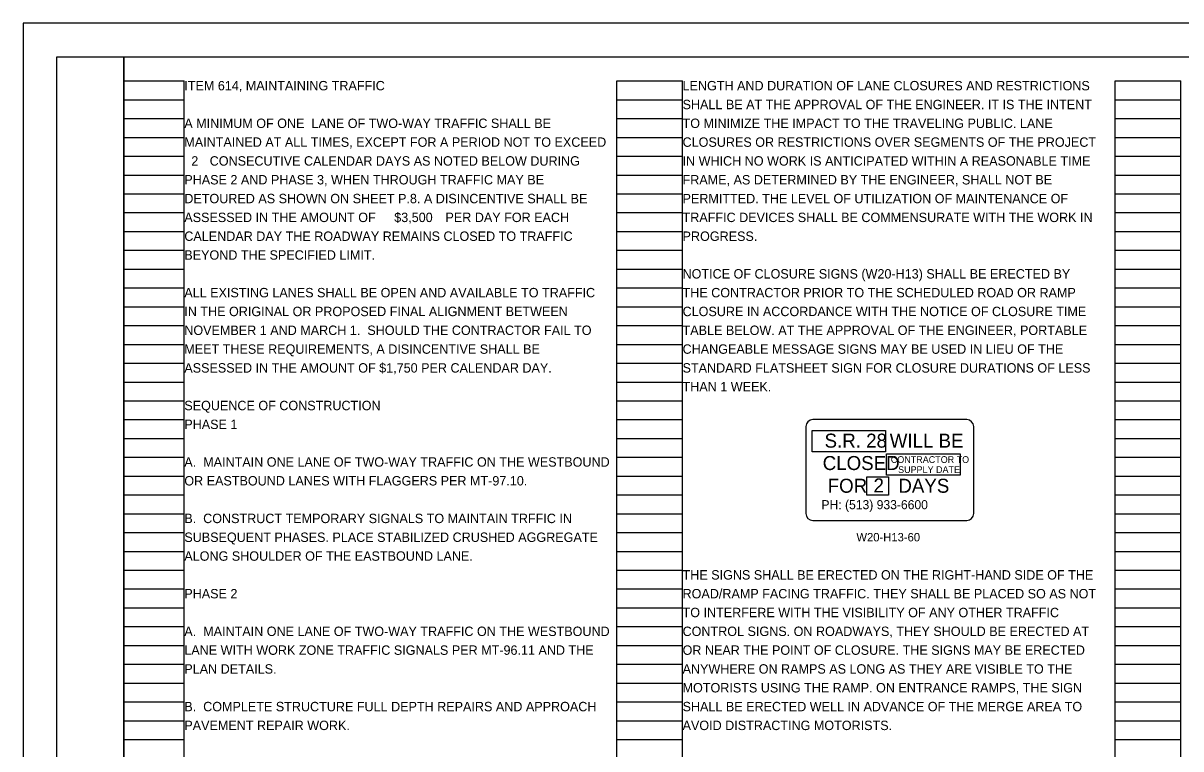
# Model space of a CAD drawing. Extents: x 0 to 34, y 0 to 33.4.
# Drawn here: x 0 to 17.24, y 11.2 to 22 of the extents above; entities that cross this region are included whole.
import ezdxf

# ---------------------------------------------------------------- set-up
doc = ezdxf.new("R2010")
doc.units = 0
for name, color, linetype in [('SH_Border', 7, 'Continuous'), ('SH_Cut_Line', 7, 'Continuous'), ('SH_Data', 7, 'Continuous'), ('SN_P_Signs', 7, 'Continuous'), ('SN_P_Text', 7, 'Continuous'), ('TX_X_20', 7, 'Continuous')]:
    doc.layers.add(name, color=color, linetype=linetype)

msp = doc.modelspace()

# ---------------------------------------------------------------- linework, layer by layer
at = {"layer": 'SH_Border'}
for points in [[(0.5, 21.5), (1.5, 21.5), (1.5, 0.5), (0.5, 0.5)], [(1.5, 21.5), (33.5, 21.5), (33.5, 0.5), (1.5, 0.5)]]:
    msp.add_lwpolyline(points, close=True, dxfattribs=at)
at = {"layer": 'SH_Cut_Line'}
msp.add_lwpolyline([(0, 0), (34, 0), (34, 22), (0, 22)], close=True, dxfattribs=at)
at = {"layer": 'SH_Data'}
for p, q in [((1.5, 0.98), (1.5, 21.14)), ((1.5, 21.14), (2.4, 21.14)), ((2.4, 0.98), (2.4, 21.14)), ((8.84, 0.98), (8.84, 21.14)), ((8.84, 21.14), (9.82, 21.14)), ((9.82, 0.98), (9.82, 21.14)), ((16.26, 0.98), (16.26, 21.14)), ((16.26, 21.14), (17.24, 21.14)), ((17.24, 0.98), (17.24, 21.14)), ((1.5, 20.86), (2.4, 20.86)), ((8.84, 20.86), (9.82, 20.86)), ((16.26, 20.86), (17.24, 20.86)), ((1.5, 20.58), (2.4, 20.58)), ((8.84, 20.58), (9.82, 20.58)), ((16.26, 20.58), (17.24, 20.58)), ((1.5, 20.3), (2.4, 20.3)), ((8.84, 20.3), (9.82, 20.3)), ((16.26, 20.3), (17.24, 20.3)), ((1.5, 20.02), (2.4, 20.02)), ((8.84, 20.02), (9.82, 20.02)), ((16.26, 20.02), (17.24, 20.02)), ((1.5, 19.74), (2.4, 19.74)), ((8.84, 19.74), (9.82, 19.74)), ((16.26, 19.74), (17.24, 19.74)), ((1.5, 19.46), (2.4, 19.46)), ((8.84, 19.46), (9.82, 19.46)), ((16.26, 19.46), (17.24, 19.46)), ((1.5, 19.18), (2.4, 19.18)), ((8.84, 19.18), (9.82, 19.18)), ((16.26, 19.18), (17.24, 19.18)), ((1.5, 18.9), (2.4, 18.9)), ((8.84, 18.9), (9.82, 18.9)), ((16.26, 18.9), (17.24, 18.9)), ((1.5, 18.62), (2.4, 18.62)), ((8.84, 18.62), (9.82, 18.62)), ((16.26, 18.62), (17.24, 18.62)), ((1.5, 18.34), (2.4, 18.34)), ((8.84, 18.34), (9.82, 18.34)), ((16.26, 18.34), (17.24, 18.34)), ((1.5, 18.06), (2.4, 18.06)), ((8.84, 18.06), (9.82, 18.06)), ((16.26, 18.06), (17.24, 18.06)), ((1.5, 17.78), (2.4, 17.78)), ((8.84, 17.78), (9.82, 17.78)), ((16.26, 17.78), (17.24, 17.78)), ((1.5, 17.5), (2.4, 17.5)), ((8.84, 17.5), (9.82, 17.5)), ((16.26, 17.5), (17.24, 17.5)), ((1.5, 17.22), (2.4, 17.22)), ((8.84, 17.22), (9.82, 17.22)), ((16.26, 17.22), (17.24, 17.22)), ((1.5, 16.94), (2.4, 16.94)), ((8.84, 16.94), (9.82, 16.94)), ((16.26, 16.94), (17.24, 16.94)), ((1.5, 16.66), (2.4, 16.66)), ((8.84, 16.66), (9.82, 16.66)), ((16.26, 16.66), (17.24, 16.66)), ((1.5, 16.38), (2.4, 16.38)), ((8.84, 16.38), (9.82, 16.38)), ((16.26, 16.38), (17.24, 16.38)), ((1.5, 16.1), (2.4, 16.1)), ((8.84, 16.1), (9.82, 16.1)), ((16.26, 16.1), (17.24, 16.1)), ((1.5, 15.82), (2.4, 15.82)), ((8.84, 15.82), (9.82, 15.82)), ((16.26, 15.82), (17.24, 15.82)), ((1.5, 15.54), (2.4, 15.54)), ((8.84, 15.54), (9.82, 15.54)), ((16.26, 15.54), (17.24, 15.54)), ((1.5, 15.26), (2.4, 15.26)), ((8.84, 15.26), (9.82, 15.26)), ((16.26, 15.26), (17.24, 15.26)), ((1.5, 14.98), (2.4, 14.98)), ((8.84, 14.98), (9.82, 14.98)), ((16.26, 14.98), (17.24, 14.98)), ((1.5, 14.7), (2.4, 14.7)), ((8.84, 14.7), (9.82, 14.7)), ((16.26, 14.7), (17.24, 14.7)), ((1.5, 14.42), (2.4, 14.42)), ((8.84, 14.42), (9.82, 14.42)), ((16.26, 14.42), (17.24, 14.42)), ((1.5, 14.14), (2.4, 14.14)), ((8.84, 14.14), (9.82, 14.14)), ((16.26, 14.14), (17.24, 14.14)), ((1.5, 13.86), (2.4, 13.86)), ((8.84, 13.86), (9.82, 13.86)), ((16.26, 13.86), (17.24, 13.86)), ((1.5, 13.58), (2.4, 13.58)), ((8.84, 13.58), (9.82, 13.58)), ((16.26, 13.58), (17.24, 13.58)), ((1.5, 13.3), (2.4, 13.3)), ((8.84, 13.3), (9.82, 13.3)), ((16.26, 13.3), (17.24, 13.3)), ((1.5, 13.02), (2.4, 13.02)), ((8.84, 13.02), (9.82, 13.02)), ((16.26, 13.02), (17.24, 13.02)), ((1.5, 12.74), (2.4, 12.74)), ((8.84, 12.74), (9.82, 12.74)), ((16.26, 12.74), (17.24, 12.74)), ((1.5, 12.46), (2.4, 12.46)), ((8.84, 12.46), (9.82, 12.46)), ((16.26, 12.46), (17.24, 12.46)), ((1.5, 12.18), (2.4, 12.18)), ((8.84, 12.18), (9.82, 12.18)), ((16.26, 12.18), (17.24, 12.18)), ((1.5, 11.9), (2.4, 11.9)), ((8.84, 11.9), (9.82, 11.9)), ((16.26, 11.9), (17.24, 11.9)), ((1.5, 11.62), (2.4, 11.62)), ((8.84, 11.62), (9.82, 11.62)), ((16.26, 11.62), (17.24, 11.62)), ((1.5, 11.34), (2.4, 11.34)), ((8.84, 11.34), (9.82, 11.34)), ((16.26, 11.34), (17.24, 11.34))]:
    msp.add_line(p, q, dxfattribs=at)
at = {"layer": 'SN_P_Signs'}
for p, q in [((14.051, 16.1), (11.759, 16.1)), ((11.655, 15.996), (11.655, 14.704)), ((14.155, 14.704), (14.155, 15.996)), ((11.759, 14.6), (14.051, 14.6))]:
    msp.add_line(p, q, dxfattribs=at)
for centre, start, end in [((11.759, 15.996), 90, 180), ((14.051, 15.996), 0, 90), ((11.759, 14.704), 180, 270), ((14.051, 14.704), 270, 360)]:
    msp.add_arc(centre, 0.104, start, end, dxfattribs=at)
at = {"layer": 'TX_X_20'}
for points in [[(11.748, 15.937), (12.842, 15.937), (12.842, 15.621), (11.748, 15.621)], [(12.859, 15.592), (13.953, 15.592), (13.953, 15.275), (12.859, 15.275)], [(12.563, 15.247), (12.885, 15.247), (12.885, 14.974), (12.563, 14.974)]]:
    msp.add_lwpolyline(points, close=True, dxfattribs=at)

# ---------------------------------------------------------------- texts
at = {"layer": 'SN_P_Signs'}
for s, height, p in [('         S.R. 28', 0.20833, (11.238, 15.683)), ('WILL BE', 0.2083, (12.905, 15.683)), ('CLOSED', 0.2083, (11.907, 15.35)), ('FOR      DAYS', 0.20833, (11.981, 15.012)), ('2', 0.208, (12.664, 15.017)), ('PH: (513) 933-6600', 0.135, (11.888, 14.767))]:
    msp.add_text(s, height=height, dxfattribs=at).set_placement(p)
at = {"layer": 'SN_P_Text'}
msp.add_text('W20-H13-60', height=0.125, dxfattribs=at).set_placement((12.409, 14.288))
at = {"layer": 'TX_X_20'}
for s, height, p in [('ITEM 614, MAINTAINING TRAFFIC', 0.14, (2.4, 21)), ('LENGTH AND DURATION OF LANE CLOSURES AND RESTRICTIONS', 0.14, (9.82, 21)), ('SHALL BE AT THE APPROVAL OF THE ENGINEER. IT IS THE INTENT', 0.14, (9.82, 20.72)), ('A MINIMUM OF ONE  LANE OF TWO-WAY TRAFFIC SHALL BE ', 0.14, (2.4, 20.44)), ('TO MINIMIZE THE IMPACT TO THE TRAVELING PUBLIC. LANE', 0.14, (9.82, 20.44)), ('MAINTAINED AT ALL TIMES, EXCEPT FOR A PERIOD NOT TO EXCEED', 0.14, (2.4, 20.16)), ('CLOSURES OR RESTRICTIONS OVER SEGMENTS OF THE PROJECT', 0.14, (9.82, 20.16)), ('  2  ', 0.14, (2.4, 19.88)), (' CONSECUTIVE CALENDAR DAYS AS NOTED BELOW DURING ', 0.14, (2.726, 19.88)), ('IN WHICH NO WORK IS ANTICIPATED WITHIN A REASONABLE TIME', 0.14, (9.82, 19.88)), ('PHASE 2 AND PHASE 3, WHEN THROUGH TRAFFIC MAY BE ', 0.14, (2.4, 19.6)), ('FRAME, AS DETERMINED BY THE ENGINEER, SHALL NOT BE', 0.14, (9.82, 19.6)), ('DETOURED AS SHOWN ON SHEET P.8. A DISINCENTIVE SHALL BE ', 0.14, (2.4, 19.32)), ('PERMITTED. THE LEVEL OF UTILIZATION OF MAINTENANCE OF', 0.14, (9.82, 19.32)), ('ASSESSED IN THE AMOUNT OF ', 0.14, (2.4, 19.04)), ('  $3,500  ', 0.14, (5.422, 19.04)), (' PER DAY FOR EACH ', 0.14, (6.237, 19.04)), ('TRAFFIC DEVICES SHALL BE COMMENSURATE WITH THE WORK IN', 0.14, (9.82, 19.04)), ('CALENDAR DAY THE ROADWAY REMAINS CLOSED TO TRAFFIC ', 0.14, (2.4, 18.76)), ('PROGRESS.', 0.14, (9.82, 18.76)), ('BEYOND THE SPECIFIED LIMIT.', 0.14, (2.4, 18.48)), ('NOTICE OF CLOSURE SIGNS (W20-H13) SHALL BE ERECTED BY', 0.14, (9.82, 18.2)), ('ALL EXISTING LANES SHALL BE OPEN AND AVAILABLE TO TRAFFIC ', 0.14, (2.4, 17.92)), ('THE CONTRACTOR PRIOR TO THE SCHEDULED ROAD OR RAMP', 0.14, (9.82, 17.92)), ('IN THE ORIGINAL OR PROPOSED FINAL ALIGNMENT BETWEEN ', 0.14, (2.4, 17.64)), ('CLOSURE IN ACCORDANCE WITH THE NOTICE OF CLOSURE TIME', 0.14, (9.82, 17.64)), ('NOVEMBER 1 AND MARCH 1.  SHOULD THE CONTRACTOR FAIL TO ', 0.14, (2.4, 17.36)), ('TABLE BELOW. AT THE APPROVAL OF THE ENGINEER, PORTABLE', 0.14, (9.82, 17.36)), ('MEET THESE REQUIREMENTS, A DISINCENTIVE SHALL BE ', 0.14, (2.4, 17.08)), ('CHANGEABLE MESSAGE SIGNS MAY BE USED IN LIEU OF THE', 0.14, (9.82, 17.08)), ('ASSESSED IN THE AMOUNT OF $1,750 PER CALENDAR DAY.', 0.14, (2.4, 16.8)), ('STANDARD FLATSHEET SIGN FOR CLOSURE DURATIONS OF LESS', 0.14, (9.82, 16.8)), ('THAN 1 WEEK.', 0.14, (9.82, 16.52)), ('SEQUENCE OF CONSTRUCTION', 0.14, (2.4, 16.24)), ('PHASE 1', 0.14, (2.4, 15.96)), ('A.  MAINTAIN ONE LANE OF TWO-WAY TRAFFIC ON THE WESTBOUND ', 0.14, (2.4, 15.4)), ('CONTRACTOR TO', 0.1, (12.921, 15.456)), ('SUPPLY DATE', 0.1, (13.03, 15.306)), ('OR EASTBOUND LANES WITH FLAGGERS PER MT-97.10.', 0.14, (2.4, 15.12)), ('B.  CONSTRUCT TEMPORARY SIGNALS TO MAINTAIN TRFFIC IN ', 0.14, (2.4, 14.56)), ('SUBSEQUENT PHASES. PLACE STABILIZED CRUSHED AGGREGATE ', 0.14, (2.4, 14.28)), ('ALONG SHOULDER OF THE EASTBOUND LANE.', 0.14, (2.4, 14)), ('THE SIGNS SHALL BE ERECTED ON THE RIGHT-HAND SIDE OF THE', 0.14, (9.82, 13.72)), ('PHASE 2', 0.14, (2.4, 13.44)), ('ROAD/RAMP FACING TRAFFIC. THEY SHALL BE PLACED SO AS NOT', 0.14, (9.82, 13.44)), ('TO INTERFERE WITH THE VISIBILITY OF ANY OTHER TRAFFIC', 0.14, (9.82, 13.16)), ('A.  MAINTAIN ONE LANE OF TWO-WAY TRAFFIC ON THE WESTBOUND ', 0.14, (2.4, 12.88)), ('CONTROL SIGNS. ON ROADWAYS, THEY SHOULD BE ERECTED AT', 0.14, (9.82, 12.88)), ('LANE WITH WORK ZONE TRAFFIC SIGNALS PER MT-96.11 AND THE ', 0.14, (2.4, 12.6)), ('OR NEAR THE POINT OF CLOSURE. THE SIGNS MAY BE ERECTED', 0.14, (9.82, 12.6)), ('PLAN DETAILS.', 0.14, (2.4, 12.32)), ('ANYWHERE ON RAMPS AS LONG AS THEY ARE VISIBLE TO THE', 0.14, (9.82, 12.32)), ('MOTORISTS USING THE RAMP. ON ENTRANCE RAMPS, THE SIGN', 0.14, (9.82, 12.04)), ('B.  COMPLETE STRUCTURE FULL DEPTH REPAIRS AND APPROACH ', 0.14, (2.4, 11.76)), ('SHALL BE ERECTED WELL IN ADVANCE OF THE MERGE AREA TO', 0.14, (9.82, 11.76)), ('PAVEMENT REPAIR WORK. ', 0.14, (2.4, 11.48)), ('AVOID DISTRACTING MOTORISTS.', 0.14, (9.82, 11.48))]:
    msp.add_text(s, height=height, dxfattribs=at).set_placement(p)

doc.saveas('drawing.dxf')
